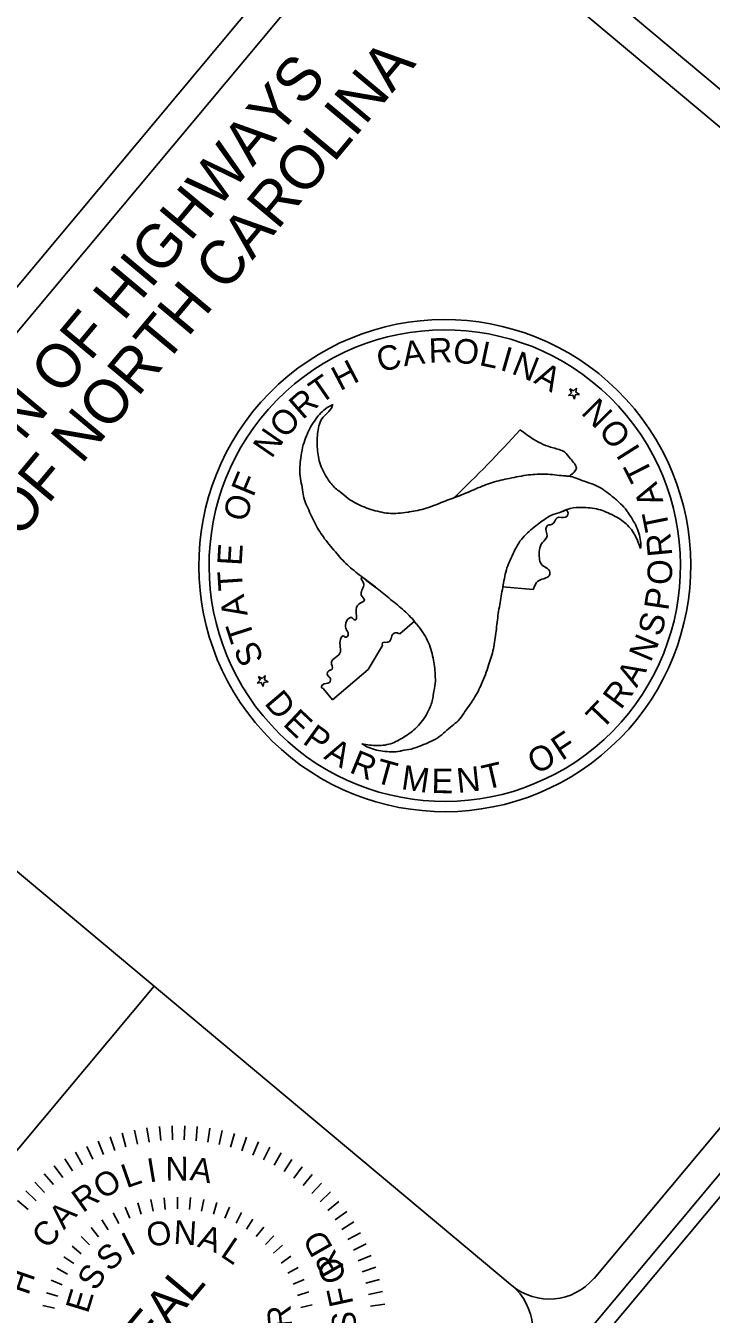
# Model space of a CAD drawing. Extents: x 555292 to 2368606, y 503623 to 1171444.
# Drawn here: x 2363476 to 2364064, y 1164815 to 1165919 of the extents above; entities that cross this region are included whole.
import ezdxf

# ---------------------------------------------------------------- set-up
doc = ezdxf.new("R2010")
doc.units = 0
for name, color, linetype in [('Old_Level_21', 7, 'Continuous'), ('Sheet Plot Border Inside CELL', 7, 'Continuous'), ('Sheet Title CELL', 7, 'Continuous')]:
    doc.layers.add(name, color=color, linetype=linetype)

msp = doc.modelspace()

# ---------------------------------------------------------------- linework, layer by layer
at = {"layer": 'Old_Level_21'}
for p, q in [((2363548.2, 1164966.8), (2363552.2, 1164955.2)), ((2363558.6, 1164970), (2363561.8, 1164958.2)), ((2363569.1, 1164972.5), (2363571.6, 1164960.6)), ((2363579.8, 1164974.4), (2363581.6, 1164962.3)), ((2363590.5, 1164975.7), (2363591.6, 1164963.5)), ((2363601.4, 1164976.3), (2363601.7, 1164964.1)), ((2363612.2, 1164976.3), (2363611.8, 1164964.1)), ((2363623, 1164975.6), (2363621.9, 1164963.4)), ((2363633.8, 1164974.3), (2363631.9, 1164962.2)), ((2363644.4, 1164972.3), (2363641.8, 1164960.3)), ((2363654.9, 1164969.6), (2363651.6, 1164957.9)), ((2363528.2, 1164958.5), (2363533.5, 1164947.5)), ((2363538.1, 1164963), (2363542.7, 1164951.6)), ((2363665.3, 1164966.4), (2363661.3, 1164954.8)), ((2363675.4, 1164962.5), (2363670.7, 1164951.2)), ((2363685.3, 1164958), (2363679.9, 1164947.1)), ((2363509.3, 1164948), (2363515.9, 1164937.7)), ((2363518.6, 1164953.5), (2363524.5, 1164942.9)), ((2363694.9, 1164953), (2363688.8, 1164942.4)), ((2363704.1, 1164947.3), (2363697.4, 1164937.1)), ((2363491.8, 1164935.2), (2363499.6, 1164925.8)), ((2363500.3, 1164941.8), (2363507.6, 1164932)), ((2363713, 1164941.2), (2363705.7, 1164931.3)), ((2363721.5, 1164934.4), (2363713.7, 1164925.1)), ((2363483.7, 1164928), (2363492, 1164919.1)), ((2363729.6, 1164927.2), (2363721.2, 1164918.3)), ((2363468.8, 1164912.3), (2363478.1, 1164904.4)), ((2363476, 1164920.4), (2363484.9, 1164912)), ((2363583.2, 1164913), (2363585.2, 1164903)), ((2363594.5, 1164914.6), (2363595.5, 1164904.5)), ((2363605.9, 1164915.2), (2363605.9, 1164905)), ((2363617.3, 1164914.7), (2363616.3, 1164904.6)), ((2363628.6, 1164913.1), (2363626.7, 1164903.1)), ((2363737.2, 1164919.5), (2363728.3, 1164911.2)), ((2363744.4, 1164911.4), (2363735, 1164903.6)), ((2363551, 1164901.5), (2363555.7, 1164892.5)), ((2363561.3, 1164906.4), (2363565.2, 1164897)), ((2363572.1, 1164910.2), (2363575, 1164900.4)), ((2363639.7, 1164910.4), (2363636.8, 1164900.6)), ((2363650.5, 1164906.6), (2363646.7, 1164897.2)), ((2363660.9, 1164901.9), (2363656.2, 1164892.8)), ((2363751.1, 1164902.9), (2363741.2, 1164895.6)), ((2363541.1, 1164895.7), (2363546.7, 1164887.2)), ((2363670.7, 1164896.1), (2363665.2, 1164887.6)), ((2363680, 1164889.4), (2363673.6, 1164881.4)), ((2363757.2, 1164893.9), (2363746.9, 1164887.3)), ((2363523.4, 1164881.4), (2363530.5, 1164874.1)), ((2363531.9, 1164889), (2363538.3, 1164881)), ((2363688.6, 1164881.8), (2363681.5, 1164874.5)), ((2363762.8, 1164884.6), (2363752.1, 1164878.7)), ((2363515.6, 1164873), (2363523.4, 1164866.4)), ((2363523.4, 1164866.4), (2363515.6, 1164873)), ((2363688.4, 1164867.2), (2363696.1, 1164873.8)), ((2363767.8, 1164875), (2363756.8, 1164869.7)), ((2363508.7, 1164863.9), (2363517.1, 1164858.1)), ((2363703.3, 1164864.4), (2363695, 1164858.6)), ((2363772.2, 1164865.1), (2363760.9, 1164860.5)), ((2363502.7, 1164854.2), (2363511.6, 1164849.2)), ((2363709.4, 1164854.7), (2363700.5, 1164849.8)), ((2363776, 1164855), (2363764.4, 1164851)), ((2363497.7, 1164843.9), (2363507, 1164839.9)), ((2363714.5, 1164844.5), (2363705.1, 1164840.4)), ((2363779.2, 1164844.6), (2363767.4, 1164841.4)), ((2363781.7, 1164834.1), (2363769.8, 1164831.6)), ((2363493.6, 1164833.2), (2363503.4, 1164830.1)), ((2363718.6, 1164833.9), (2363708.9, 1164830.7)), ((2363783.7, 1164823.4), (2363771.6, 1164821.6)), ((2363490.7, 1164822.2), (2363500.6, 1164820)), ((2363721.6, 1164822.8), (2363711.7, 1164820.6))]:
    msp.add_line(p, q, dxfattribs=at)
at = {"layer": 'Sheet Plot Border Inside CELL'}
msp.add_lwpolyline([(2359232.5, 1159130.5), (2364578.6, 1165521.9), (2360532, 1168906.6), (2355185.9, 1162515.2)], close=True, dxfattribs=at)
at = {"layer": 'Sheet Title CELL'}
for p, q in [((2359196.5, 1160588.2), (2363751.8, 1166034.2)), ((2363273, 1165422.8), (2363771, 1166018.2)), ((2363945.7, 1165606.1), (2363942.5, 1165607.8)), ((2363942.5, 1165607.8), (2363943.9, 1165604.5)), ((2363948.2, 1165608.6), (2363945.7, 1165606.1)), ((2363947.6, 1165605), (2363948.2, 1165608.6)), ((2363943.9, 1165604.5), (2363941.3, 1165602.1)), ((2363941.3, 1165602.1), (2363944.9, 1165602.5)), ((2363944.9, 1165602.5), (2363946.5, 1165599.2)), ((2363946.5, 1165599.2), (2363947.1, 1165602.7)), ((2363947.1, 1165602.7), (2363950.7, 1165603.1)), ((2363950.7, 1165603.1), (2363947.6, 1165605)), ((2363990.6, 1165598.9), (2363990.6, 1165598.9)), ((2363738.8, 1165594.7), (2363738.8, 1165594.1)), ((2363738.8, 1165594.7), (2363738.8, 1165594.1)), ((2363842.9, 1165514.5), (2363842.9, 1165514.5)), ((2363910.9, 1165435.9), (2363884.9, 1165438.1)), ((2363884.9, 1165438.1), (2363884.9, 1165438.1)), ((2363809.1, 1165408.9), (2363796.7, 1165397.8)), ((2363781.9, 1165387.8), (2363769.5, 1165367.3)), ((2363769.5, 1165367.3), (2363739, 1165341.4)), ((2363674.2, 1165355.7), (2363677, 1165358.2)), ((2363677.9, 1165356.1), (2363674.2, 1165355.7)), ((2363677, 1165358.2), (2363675.4, 1165361.3)), ((2363675.4, 1165361.3), (2363678.6, 1165359.7)), ((2363679.5, 1165352.8), (2363677.9, 1165356.1)), ((2363678.6, 1165359.7), (2363681.3, 1165362.2)), ((2363680.1, 1165356.3), (2363679.5, 1165352.8)), ((2363683.7, 1165356.7), (2363680.1, 1165356.3)), ((2363681.3, 1165362.2), (2363680.6, 1165358.5)), ((2363680.6, 1165358.5), (2363683.7, 1165356.7)), ((2363892.9, 1164839.1), (2363279.3, 1165352.4)), ((2363739, 1165341.4), (2363730.8, 1165351.1)), ((2362878.1, 1164249.5), (2363586, 1165095.8))]:
    msp.add_line(p, q, dxfattribs=at)
for points in [[(2364490.3, 1165514.3), (2360540, 1168818.4)], [(2364455.1, 1165511.2), (2363841.4, 1166024.4)], [(2359748.8, 1159767.7), (2364496.6, 1165443.8)], [(2363963.4, 1164845.4), (2364461.3, 1165440.7)]]:
    msp.add_lwpolyline(points, dxfattribs=at)
for centre, radius, start, end in [((2363835.2, 1165456.4), 210.9, 42.5106, 222.5106), ((2363835.2, 1165456.4), 202.1, 42.5106, 222.5106), ((2363835.2, 1165456.4), 210.9, 222.5106, 42.5106), ((2363835.2, 1165456.4), 202.1, 222.5106, 42.5106), ((2363075.8, 1166319.2), 1111.8, 313.6282, 317.8342), ((2363075.8, 1166319.2), 1111.8, 308.1891, 308.2887), ((2363924.8, 1164877.7), 50, 230.0895, 320.0895), ((2363860.6, 1164801), 50, 320.0895, 50.0895)]:
    msp.add_arc(centre, radius, start, end, dxfattribs=at)
for points in [[(2363738.8, 1165594.1), (2363734.4, 1165591.8), (2363724.5, 1165581.9), (2363717.1, 1165568.9), (2363716.6, 1165567.6), (2363713.9, 1165560), (2363712.1, 1165550.8), (2363711, 1165535.1), (2363713.6, 1165519.3), (2363714.8, 1165512.8), (2363717.7, 1165505.9), (2363724.3, 1165491.8), (2363732.2, 1165479.5), (2363742.8, 1165466.5), (2363753, 1165455.8), (2363765, 1165446.3), (2363777.2, 1165436.9), (2363788.7, 1165427.5), (2363800.5, 1165417.7), (2363810.8, 1165406.6), (2363811.6, 1165405.6), (2363820.5, 1165392), (2363825.2, 1165377.2), (2363827, 1165362.9), (2363827, 1165355.5), (2363825.5, 1165346.7), (2363824.7, 1165341.6), (2363821, 1165331.6), (2363812.6, 1165319.3), (2363801.7, 1165310.4), (2363790.3, 1165304.3), (2363777.4, 1165302.1), (2363764.2, 1165303.7)], [(2364003.1, 1165471), (2364003.2, 1165475.7), (2363999.7, 1165489.3), (2363992.1, 1165502.3), (2363991.3, 1165503.5), (2363985.9, 1165509.5), (2363978.8, 1165515.7), (2363965.8, 1165524.6), (2363950.9, 1165530.1), (2363944.6, 1165532.4), (2363937.1, 1165533.4), (2363921.6, 1165534.8), (2363907.1, 1165534.1), (2363890.5, 1165531.2), (2363876.2, 1165527.7), (2363861.9, 1165522.2), (2363847.7, 1165516.3), (2363833.9, 1165511.1), (2363819.3, 1165505.6), (2363804.7, 1165502.4), (2363803.4, 1165502.2), (2363787, 1165501.3), (2363771.9, 1165504.6), (2363758.5, 1165510.1), (2363752.4, 1165513.9), (2363745.4, 1165519.6), (2363741.3, 1165522.8), (2363734.6, 1165531.1), (2363728.1, 1165544.5), (2363725.9, 1165558.3), (2363726.3, 1165571.2), (2363730.9, 1165583.6), (2363738.8, 1165594.1), (2363738.8, 1165594.7)], [(2363899.9, 1165572.9), (2363911.6, 1165564.5), (2363928.2, 1165557.3), (2363937.8, 1165553.8), (2363943, 1165548), (2363948, 1165539.9), (2363942, 1165533.1)], [(2363942, 1165533), (2363937.1, 1165533.4), (2363921.6, 1165534.8), (2363907.1, 1165534.1), (2363890.5, 1165531.2), (2363876.2, 1165527.7), (2363861.9, 1165522.2), (2363847.7, 1165516.3), (2363842.9, 1165514.5)], [(2363764.2, 1165303.7), (2363768.5, 1165301.2), (2363782, 1165297.4), (2363796.9, 1165297.4), (2363798.2, 1165297.7), (2363806.3, 1165299.2), (2363815.2, 1165302.3), (2363829.4, 1165309.1), (2363841.5, 1165319.2), (2363846.7, 1165323.5), (2363851.4, 1165329.7), (2363860.1, 1165342.3), (2363866.8, 1165355.1), (2363872.8, 1165371), (2363876.9, 1165385), (2363879.2, 1165400.3), (2363881.1, 1165415.5), (2363883.6, 1165430.2), (2363886.3, 1165445.3), (2363890.6, 1165459.7), (2363891.3, 1165461.1), (2363898.6, 1165475.7), (2363909, 1165487), (2363920.3, 1165495.7), (2363926.8, 1165499.6), (2363935.2, 1165502.4), (2363940.1, 1165504.6), (2363950.6, 1165506.2), (2363965.3, 1165505), (2363978.4, 1165500.1), (2363989.5, 1165493.2), (2363997.9, 1165483.1), (2364003.1, 1165471)], [(2363884.9, 1165438.1), (2363886.3, 1165445.3), (2363890.6, 1165459.7), (2363891.3, 1165461.1), (2363898.6, 1165475.7), (2363909, 1165487), (2363920.3, 1165495.7), (2363926.8, 1165499.6), (2363935.2, 1165502.4), (2363939.7, 1165504.4)], [(2363939.7, 1165504.3), (2363940.8, 1165500.3), (2363938.6, 1165497.9), (2363931.5, 1165497.4), (2363927.4, 1165491.8), (2363923.9, 1165491), (2363922.3, 1165489.7), (2363922.9, 1165481.8), (2363918.9, 1165476.1), (2363916.3, 1165462.8), (2363917.8, 1165457.8), (2363925.3, 1165450.9), (2363924.6, 1165447.6), (2363921.9, 1165445.8), (2363915.1, 1165443.2), (2363910.9, 1165435.9)], [(2363730.8, 1165351.1), (2363729.7, 1165351.6), (2363730.3, 1165354.1), (2363736.3, 1165356.3), (2363736.8, 1165360.2), (2363735, 1165362), (2363735, 1165365.5), (2363738.5, 1165367.7), (2363738.1, 1165373.6), (2363740, 1165376.5), (2363745.3, 1165381.3), (2363745.8, 1165393.3), (2363748.1, 1165396.1), (2363750.2, 1165395), (2363752.1, 1165396.1), (2363750.1, 1165403.8), (2363750.1, 1165405.1), (2363753.2, 1165411.5), (2363755.3, 1165411.8), (2363757.8, 1165409.8), (2363758.9, 1165410), (2363759.5, 1165412.6), (2363759.1, 1165417.4), (2363761.2, 1165423.1), (2363766.3, 1165426.8), (2363763.6, 1165431.2), (2363765.7, 1165439.7), (2363764.8, 1165442.9), (2363763.1, 1165445.3)], [(2363764.7, 1165446.6), (2363765, 1165446.3), (2363777.2, 1165436.9), (2363788.7, 1165427.5), (2363800.5, 1165417.7), (2363809, 1165408.9)], [(2363796.7, 1165397.8), (2363793.4, 1165398.9), (2363790.4, 1165397.4), (2363788.7, 1165392.8), (2363786.1, 1165390.7), (2363781.7, 1165390.2), (2363781.9, 1165387.8)]]:
    msp.add_spline(points, degree=3, dxfattribs=at)

# ---------------------------------------------------------------- texts
at = {"layer": 'Old_Level_21'}
for s, height, rotation, p in [('I', 20.4, 9.5888, (2363581.9, 1164927.6)), ('N', 20.4, 0.2943, (2363595.8, 1164929.2)), ('A', 20.4, 350.5268, (2363616, 1164929.9)), ('O', 20.4, 32.3005, (2363542, 1164912.5)), ('L', 20.4, 19.1642, (2363562.3, 1164922.6)), ('R', 20.4, 35.3573, (2363524.8, 1164901.2)), ('A', 20.4, 47.3666, (2363508.7, 1164886.6)), ('C', 20.4, 47.3666, (2363494.1, 1164869.8)), ('O', 20.4, 11.7691, (2363581.8, 1164871.8)), ('N', 20.4, 356.4728, (2363602.3, 1164875.1)), ('A', 20.4, 341.1766, (2363622.3, 1164872.9)), ('I', 20.4, 27.0653, (2363565.1, 1164864.3)), ('L', 20.4, 325.8803, (2363641.9, 1164865)), (' RD', 20.36, 119.6821, (2363753.3, 1164848.1)), ('S', 20.4, 42.3616, (2363547.9, 1164850.6)), ('S', 20.4, 57.6578, (2363536.1, 1164833.9)), ('O ', 20.36, 111.0093, (2363751.5, 1164845.7)), ('H', 20.4, 71.0773, (2363478, 1164830.3)), ('SEAL', 30.57, 50.0097, (2363564, 1164760.9)), ('E', 20.4, 72.954, (2363529.2, 1164814.7)), ('F', 20.4, 102.2167, (2363757, 1164823.7)), ('R', 20.4, 94.5746, (2363704.4, 1164803.6)), ('S', 20.4, 93.3341, (2363759.4, 1164799.6))]:
    msp.add_text(s, height=height, rotation=rotation, dxfattribs=at).set_placement(p)
at = {"layer": 'Sheet Title CELL'}
for s, height, rotation, p in [('STATE OF NORTH CAROLINA', 37.497, 50.0895, (2363357.4, 1165343.8)), ('DIVISION OF HIGHWAYS', 37.497, 50.0895, (2363355.9, 1165421.4)), ('R', 21, 1.4487, (2363821.6, 1165630.2)), ('O', 21.1, 354.3291, (2363841.7, 1165630.6)), ('C', 21, 15.3097, (2363780, 1165621.8)), ('A', 21, 7.8126, (2363800.3, 1165627.2)), ('L', 21, 348.0954, (2363864, 1165628.4)), ('I', 21.1, 344.1061, (2363881.7, 1165624.3)), ('H', 21, 27.652, (2363745.4, 1165605.8)), ('N', 21, 338.406, (2363891.5, 1165621.3)), ('T', 21.1, 34.7367, (2363728.4, 1165594.2)), ('A', 21, 330.974, (2363910.7, 1165613.6)), ('R', 21, 41.3864, (2363713.3, 1165580.9)), ('N', 21, 134.7188, (2363980.5, 1165587.3)), ('O', 21.1, 47.9963, (2363698.4, 1165564.4)), ('N', 21, 55.4944, (2363686.7, 1165547.5)), ('O', 20.9, 127.4707, (2363996.1, 1165567.3)), ('I', 21.1, 122.3351, (2364003.4, 1165556)), ('T', 21, 116.6852, (2364014.2, 1165534.8)), ('F', 21.1, 67.5813, (2363670.9, 1165514.5)), ('A', 21.1, 109.6008, (2364022.8, 1165511.4)), ('O', 21, 74.7282, (2363665, 1165493.1)), ('T', 21, 101.5137, (2364028, 1165488.1)), ('R', 21.1, 95.414, (2364030.4, 1165465)), ('E', 21, 86.6676, (2363661, 1165456)), ('O', 21.1, 88.2248, (2364029.8, 1165439.6)), ('T', 21, 93.7832, (2363662.2, 1165435.5)), ('A', 21.1, 100.8384, (2363666.3, 1165414.1)), ('P', 21, 81.5329, (2364026.7, 1165417.3)), ('S', 20.9, 74.341, (2364020.5, 1165394.9)), ('T', 21.1, 107.8907, (2363672.3, 1165394.5)), ('N', 21, 67.1305, (2364011.7, 1165372.8)), ('S', 21, 114.2669, (2363680.5, 1165376.2)), ('A', 21, 60.0989, (2363999.7, 1165351.1)), ('R', 21, 53.3458, (2363986.1, 1165332.2)), ('D', 21, 310.3636, (2363679.8, 1165338.2)), ('E', 20.9, 316.6515, (2363695.6, 1165320)), ('T', 21, 46.3892, (2363969.8, 1165314.8)), ('P', 21, 324.1839, (2363712.4, 1165304.6)), ('F', 21, 33.4799, (2363935.6, 1165288.8)), ('A', 21, 330.7765, (2363730.7, 1165291.4)), ('R', 21, 337.8451, (2363752.5, 1165279.5)), ('O', 21, 26.3147, (2363912.9, 1165277.2)), ('T', 21, 344.4956, (2363774.1, 1165271)), ('T', 21, 13.011, (2363870, 1165264.2)), ('M', 21, 351.7307, (2363797.2, 1165264.9)), ('E', 21, 359.1975, (2363823.7, 1165261.5)), ('N', 21.1, 6.169, (2363846.4, 1165261.5))]:
    msp.add_text(s, height=height, rotation=rotation, dxfattribs=at).set_placement(p)

doc.saveas('drawing.dxf')
